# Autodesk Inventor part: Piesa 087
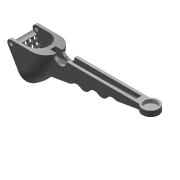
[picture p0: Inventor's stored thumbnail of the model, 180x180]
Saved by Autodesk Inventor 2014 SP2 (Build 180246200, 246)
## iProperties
Created: 2009-02
Part Number: Piesa 087
Document SubType Name: Modeling
Designer: Costel
Material: Steel, Cast
Density: 7.85 g/cm^3
Appearance: Steel - Cast
Mass: 236.747 g
Surface Area: 137.474 cm^2
Volume: 30.1589 cm^3
Author: Costel
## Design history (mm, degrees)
sketch "Sketch1"
  geometry: L1 (-4.6, 0)-(59.8, 0) reference; L2 (0, -18.6)-(0, 24.8) reference; L3 (30.5, 15.5)-(0, 15.5); L4 (30.5, -15.5)-(0, -15.5); L5 (21.5, 12.5)-(0, 12.5); L6 (21.5, -12.5)-(0, -12.5); L7 (0, 15.5)-(0, 12.5); L8 (0, -12.5)-(0, -15.5); A1 r 12.5 centre (21.5, 0) between (21.5, -12.5) and (21.5, 12.5); A2 r 15.5 centre (30.5, 0) between (30.5, -15.5) and (30.5, 15.5)
  constraints: 12 end point, 4 perpendicular, 4 point on circle, 4 tangent, 3 point on line, 2 centre point, 2 collinear, 1 parallel, 1 other
  dimensions: "d0" = 12.5 radius of A1; "d1" = 15.5 radius of A2; "d3" = 21.5 distance from line of A1.centre L2 (computed from d0); "d4" = 30.5 distance from line of L2 A2.centre (computed from d1)
revolve "Revolution1" sketch "Sketch1" stored, may be unused: angle "d6" = 60 deg
sketch "Sketch2"
  geometry: L1 (4.6, 0)-(-59.8, 0) reference; L2 (0, -43.821)-(0, 11.951) reference; L3 (-34, 0)-(-146, 0); L4 (-146, 0)-(-146, -6); L5 (-146, -6)-(-136.249, -6); L6 (-22.532, -31.128)-(-109.642, -15.769); L7 (-62.28, -19.043)-(-21.664, -26.204); L8 (-136.249, -6)-(-115.875, -9.592); L9 (-21.664, -26.204)-(-22.532, -31.128); L10 (-39.837, -23)-(-40.705, -27.924); A1 r 34 centre (0, 0) between (-34, 0) and (-17, -29.445) reference; A2 r 34 centre (0, 0) between (-34, 0) and (-21.664, -26.204); A3 r 7 centre (-70.25, -22.715) between (-65.657, -17.432) and (-74.323, -17.022); A4 r 7 centre (-89.946, -19.242) between (-84.171, -15.285) and (-94.019, -13.549); A5 r 7 centre (-109.642, -15.769) between (-103.867, -11.812) and (-112.151, -9.234); A6 r 7 centre (-61.064, -12.149) between (-65.657, -17.432) and (-62.28, -19.043); A7 r 7 centre (-114.66, -2.699) between (-115.875, -9.592) and (-112.151, -9.234); A8 r 46 centre (0, 0) between (-46, 0) and (-23, -39.837) reference; A9 r 7 centre (-98.092, -7.856) between (-103.867, -11.812) and (-94.019, -13.549); A10 r 7 centre (-78.396, -11.329) between (-84.171, -15.285) and (-74.323, -17.022)
  constraints: 18 point on circle, 16 end point, 9 tangent, 8 centre point, 5 point on line, 4 equal radius, 4 perpendicular, 2 coincident, 2 parallel
  dimensions: "d7" = 146 distance between parallel lines of L2 L4; "d8" = 6 distance between parallel lines of L3 L5; "d18" = 10 deg angle of L3 L8; "d25" = 5 distance of L7.end L6.start; "d27" = 20 distance of A3.centre A4.centre; "d28" = 20 distance of L6.end A4.centre (= d27); "d29" = 7 radius of A3; "d30" = 7 radius of A6; "d92" = 30 distance from line of A3.centre L10; "d93" = 23 distance from line of L3 L10.start; "d95" = 7 radius of A9
extrude "Extrusion1" join sketch "Sketch2" stored distance "d31" = 12; taper "d32" = 0 deg
sketch "Sketch3"
  geometry: L1 (-31, -15.5)-(186, -15.5) reference; L2 (0, -37.2)-(0, 6.2) reference; C1 r 9 at (146, -15.5)
  constraints: 1 centre point, 1 point on line
  dimensions: "d33" = 18 diameter of C1; "d36" = 146 distance from line of L2 C1.centre (= d7)
extrude "Extrusion2" join sketch "Sketch3" distance "d34" = 6; taper "d35" = 0 deg
sketch "Sketch4"
  geometry: C1 r 7 at (146, -15.5); A1 r 9 centre (146, -15.5) between (139.292, -21.5) and (139.292, -9.5) reference
  constraints: 1 centre point, 1 coincident
  dimensions: "d37" = 14 diameter of C1
extrude "Extrusion3" cut sketch "Sketch4" distance "d38" = 4; taper "d39" = 0 deg
sketch "Sketch5"
  geometry: L1 (0, -43.821)-(0, 11.951) reference; L2 (15.5, 0)-(-201.5, 0) reference; L3 (-38.105, -2)-(-130.892, -2); L4 (-130.997, -3.997)-(-40.461, -8.742); L5 (-38.359, -6.849)-(-38, 0); L6 (-132.89, -2.105)-(-133, 0); A1 r 2 centre (-130.892, -2) between (-132.89, -2.105) and (-130.997, -3.997); A2 r 2 centre (-40.356, -6.745) between (-40.461, -8.742) and (-38.359, -6.849)
  constraints: 8 end point, 5 tangent, 4 point on circle, 3 point on line, 2 centre point, 1 coincident, 1 parallel
  dimensions: "d40" = 2 distance between parallel lines of L2 L3; "d41" = 3 deg angle of L3 L4; "d42" = 3 deg angle of L1 L5; "d43" = 3 deg angle of L1 L6; "d44" = 38 distance from line of L1 L5.end; "d45" = 95 distance of L6.end L5.end; "d46" = 2 radius of A2
extrude "Extrusion4" cut sketch "Sketch5" stored distance "d47" = 6; taper "d48" = 0 deg
sketch "Sketch6"
  geometry: L1 (15.5, 0)-(-201.5, 0) reference; L2 (0, -43.821)-(0, 11.951) reference; A1 r 7 centre (-52, 0) between (-59, 0) and (-45, 0)
  constraints: 3 point on line, 2 point on circle, 1 centre point
  dimensions: "d49" = 52 distance from line of L2 A1.centre; "d50" = 7 radius of A1
extrude "Extrusion5" cut sketch "Sketch6" stored distance "d51" = 6; taper "d52" = 0 deg
sketch "Sketch7"
  geometry: L1 (0, 0)-(-10.75, -18.62) reference; L2 (-3.464, 0)-(-19.532, -27.83); L3 (15.5, 0)-(-201.5, 0) reference; L4 (-3.464, 0)-(0, 0); L5 (0, 0)-(-17, -29.445); A1 r 34 centre (0, 0) between (-34, 0) and (-17, -29.445) reference; A2 r 34 centre (0, 0) between (-19.532, -27.83) and (-17, -29.445)
  constraints: 6 end point, 3 point on circle, 2 parallel, 1 centre point, 1 coincident, 1 collinear, 1 point on line
  dimensions: "d53" = 3 distance between parallel lines of L1 L2
extrude "Extrusion6" join sketch "Sketch7" stored distance "d54" = 6; taper "d55" = 0 deg
fillet "Fillet1" dims "d56" = 4
sketch "Sketch8"
  geometry: A1 r 4 centre (0, -4) between (0, 0) and (-2.803, -1.146) reference; 1 further point
  constraints: 1 coincident, 1 vertical alignment, 2 other
extrude "Extrusion7" cut sketch "Sketch8" stored distance "d57" = 6; taper "d58" = 0 deg
hole "Hole1" diameter "d61" = 4; stored, may be unused: countersink angle "d65" = 90 deg, drill point angle "d67" = 118 deg; dims "d59" = 10, "d60" = 10, "d62" = 6, "d63" = 4, "d64" = 2, "d66" = 8
sketch "Sketch9"
  geometry: L1 (23.572, 12.5)-(23.572, -12.5) reference; L2 (52.9, 0)-(-103.9, 0) reference; L3 (17.572, 10)-(7.572, 10); 2 further points
  constraints: 3 end point, 1 coincident, 1 midpoint, 1 parallel
  dimensions: "d68" = 6 distance from line of L1 L3.start; "d69" = 5 distance of point (17.572, 10) point (12.572, 10); "d70" = 5 distance of point (12.572, 10) L3.end; "d79" = 10 distance between parallel lines of L2 L3
hole "Hole2" sketch "Sketch9" at (17.572, 10), (12.572, 10), (7.572, 10) diameter "d72" = 4; stored, may be unused: countersink angle "d76" = 90 deg, drill point angle "d78" = 118 deg; dims "d73" = 6, "d74" = 4, "d75" = 2, "d77" = 8
pattern_linear "Rectangular Pattern1" dims "d82" = 5
sketch "Sketch10"
  geometry: C1 r 2 at (7.572, -5) reference; C2 r 2 at (7.572, 0) reference; C3 r 2 at (7.572, 5) reference; C4 r 2 at (7.572, 10) reference; 3 further points
  constraints: 3 horizontal alignment, 2 vertical alignment
  dimensions: "d83" = 5 horizontal distance of C4.centre point (2.572, 5)
hole "Hole3" sketch "Sketch10" at (2.572, 5), (2.572, 0), (2.572, -5) diameter "d84" = 4; stored, may be unused: countersink angle "d88" = 90 deg, drill point angle "d90" = 118 deg; dims "d85" = 6, "d86" = 4, "d87" = 2, "d89" = 8
body "Solid1"
other parameters: "d9" = 10 deg
